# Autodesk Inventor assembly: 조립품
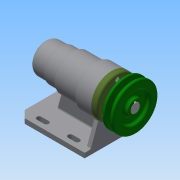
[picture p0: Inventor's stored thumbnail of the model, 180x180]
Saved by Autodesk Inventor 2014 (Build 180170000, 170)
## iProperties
Created: 2017-09
Part Number: 조립품
Document SubType Name: Assembly
Designer: net
Author: net
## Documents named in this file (12)
- C:\Users\net\Desktop\470907v1018\조립품.iam
- C:\Users\net\Desktop\470907v1018\본체.ipt
- C:\Users\net\Desktop\470907v1018\베어링 51202.ipt
- C:\Users\net\Desktop\470907v1018\축.ipt
- C:\Users\net\Desktop\470907v1018\볼트 M4 x 12.ipt
- C:\Users\net\Desktop\470907v1018\어댑터슬리브.ipt
- C:\Users\net\Desktop\470907v1018\베어링 6004.ipt
- C:\Users\net\Desktop\470907v1018\커버.ipt
- C:\Users\net\Desktop\470907v1018\키 5 x 5 x 16.ipt
- C:\Users\net\Desktop\470907v1018\V벨트풀리.ipt
- C:\Users\net\Desktop\470907v1018\멈춤나사 M3x8.ipt
- C:\Users\net\Desktop\470907v1018\오일 실 20x35x7.ipt
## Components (1 placed, 1 different names)
1. V벨트풀리:1
